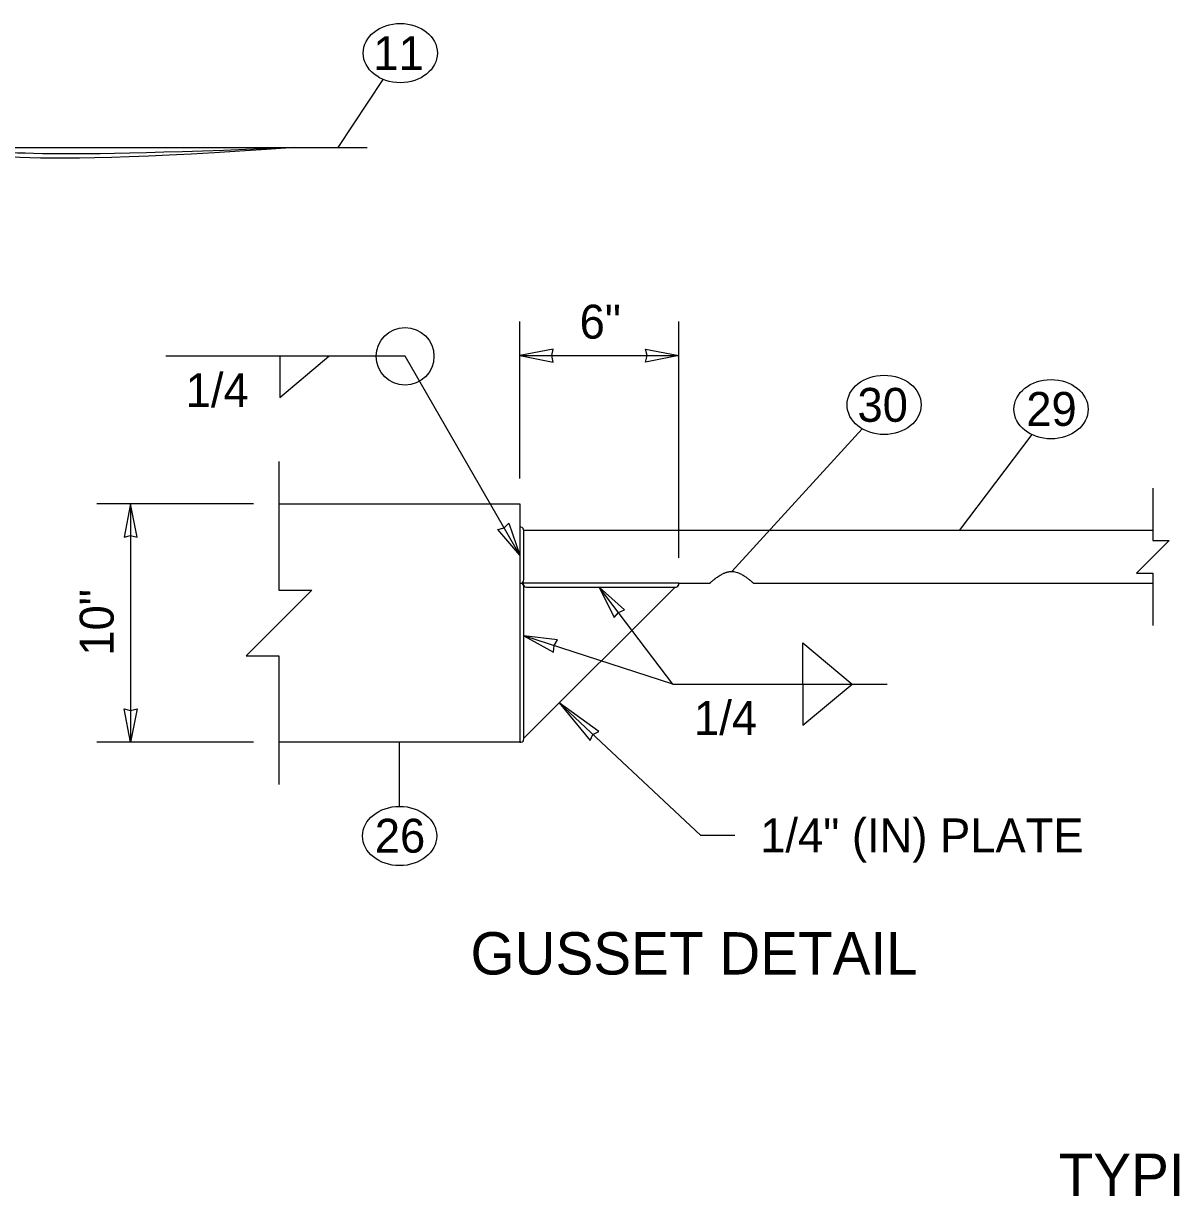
# Model space of a CAD drawing. Extents: x 99862 to 104211, y 98939 to 102076.
# Drawn here: x 102205 to 102749, y 100846 to 101400 of the extents above; entities that cross this region are included whole.
import ezdxf

# ---------------------------------------------------------------- set-up
doc = ezdxf.new("R2010")
doc.units = 0
for name, color, linetype in [('Level 12', 7, 'Continuous'), ('Level 15', 7, 'Continuous'), ('Level 16', 7, 'Continuous'), ('Level 2', 7, 'Continuous'), ('Level 20', 7, 'Continuous'), ('Level 3', 7, 'Continuous'), ('Level 4', 7, 'Continuous'), ('Level 9', 7, 'Continuous')]:
    doc.layers.add(name, color=color, linetype=linetype)

msp = doc.modelspace()

# ---------------------------------------------------------------- linework, layer by layer
at = {"layer": 'Level 12'}
msp.add_line((102123.27, 101341.26), (102367.23, 101341.26), dxfattribs=at)
at = {"layer": 'Level 15'}
for p, q in [((102374.75, 101373.43), (102353.49, 101341.26)), ((102439.43, 101185.03), (102439.43, 101259.03)), ((102514.43, 101147.53), (102514.43, 101259.03)), ((102385.21, 101242.68), (102272.21, 101242.68)), ((102439.43, 101148.76), (102385.21, 101242.68)), ((102439.43, 101243.03), (102514.43, 101243.03)), ((102600.94, 101208.46), (102539.33, 101141.08)), ((102680.98, 101205.72), (102646.64, 101160.43)), ((102313.65, 101173.03), (102239.65, 101173.03)), ((102255.65, 101173.03), (102255.65, 101060.53)), ((102511.56, 101087.97), (102476.83, 101133.7)), ((102511.56, 101087.97), (102441.26, 101110.74)), ((102511.56, 101087.97), (102612.69, 101087.97)), ((102457.93, 101079.03), (102524.79, 101016.5)), ((102313.65, 101060.53), (102239.65, 101060.53)), ((102382.54, 101030.22), (102382.54, 101060.53)), ((102540.79, 101016.5), (102524.79, 101016.5))]:
    msp.add_line(p, q, dxfattribs=at)
for points in [[(102439.43, 101243.03), (102455.15, 101239.95), (102454.43, 101243.03), (102455.15, 101246.11)], [(102514.43, 101243.03), (102498.7, 101239.95), (102499.43, 101243.03), (102498.7, 101246.11)], [(102255.65, 101173.03), (102252.57, 101157.3), (102255.65, 101158.03), (102258.74, 101157.3)], [(102439.43, 101148.76), (102428.9, 101160.84), (102431.93, 101161.75), (102434.24, 101163.92)], [(102476.83, 101133.7), (102483.89, 101119.31), (102485.9, 101121.76), (102488.8, 101123.04)], [(102441.26, 101110.79), (102455.26, 101102.99), (102455.52, 101106.15), (102457.17, 101108.86)], [(102457.93, 101079.03), (102472.56, 101061.25), (102473.83, 101064.16), (102476.64, 101065.61)], [(102255.65, 101060.53), (102252.57, 101076.25), (102255.65, 101075.53), (102258.74, 101076.25)]]:
    msp.add_lwpolyline(points, close=True, dxfattribs=at)
for points in [[(102326.05, 101242.68), (102326.05, 101223.21), (102349.28, 101242.68)], [(102325.65, 101193.03), (102325.65, 101132.27), (102341.14, 101132.27), (102310.17, 101101.29), (102325.65, 101101.29), (102325.65, 101040.53)], [(102738.12, 101180.43), (102738.12, 101155.72), (102745.86, 101155.72), (102730.37, 101140.24), (102738.12, 101140.24), (102738.12, 101115.53)], [(102572.93, 101087.97), (102572.93, 101107.44), (102596.16, 101087.97)], [(102572.93, 101087.97), (102572.93, 101068.5), (102596.16, 101087.97)]]:
    msp.add_lwpolyline(points, dxfattribs=at)
msp.add_circle((102385.21, 101242.68), 13.61, dxfattribs=at)
at = {"layer": 'Level 16'}
for points in [[(102333.14, 101341.26), (102186.03, 101330.44), (102169.52, 101348.95), (102146.65, 101342.91), (102142.45, 101341.28)], [(102333.14, 101341.26), (102203.46, 101335.63), (102169.6, 101342.41), (102160.42, 101347.25), (102150.05, 101341.31)]]:
    msp.add_open_spline(points, degree=3, dxfattribs=at)
at = {"layer": 'Level 2'}
for p, q in [((102325.65, 101173.03), (102439.43, 101173.03)), ((102439.43, 101173.03), (102439.43, 101060.53)), ((102439.43, 101060.53), (102325.65, 101060.53))]:
    msp.add_line(p, q, dxfattribs=at)
at = {"layer": 'Level 20'}
for centre in [(102382.93, 101385.81), (102611.27, 101219.76), (102690.06, 101217.69), (102382.61, 101016.22)]:
    msp.add_ellipse(centre, major_axis=(-17.5, 0), ratio=0.8, dxfattribs=at)
at = {"layer": 'Level 3'}
msp.add_line((102512.6, 101133.7), (102441.26, 101062.36), dxfattribs=at)
at = {"layer": 'Level 4'}
for p, q in [((102738.12, 101160.43), (102441.26, 101160.43)), ((102514.41, 101135.53), (102528.99, 101135.53)), ((102549.67, 101135.53), (102738.12, 101135.53))]:
    msp.add_line(p, q, dxfattribs=at)
msp.add_open_spline([(102528.99, 101135.53), (102528.99, 101135.53), (102528.99, 101135.53), (102528.99, 101135.53), (102529.01, 101135.55), (102529.08, 101135.61), (102529.19, 101135.71), (102529.36, 101135.86), (102529.56, 101136.04), (102529.68, 101136.14), (102530.07, 101136.48), (102530.39, 101136.76), (102530.94, 101137.21), (102531.14, 101137.37), (102531.55, 101137.69), (102532.2, 101138.19), (102532.95, 101138.72), (102534.02, 101139.41), (102534.6, 101139.74), (102535.52, 101140.19), (102535.83, 101140.33), (102536.49, 101140.58), (102536.83, 101140.7), (102537.52, 101140.88), (102537.87, 101140.96), (102538.59, 101141.06), (102538.96, 101141.08), (102540.06, 101141.08), (102540.77, 101140.98), (102542.17, 101140.61), (102542.82, 101140.35), (102544.05, 101139.75), (102544.63, 101139.41), (102545.7, 101138.73), (102546.2, 101138.38), (102546.89, 101137.86), (102547.11, 101137.69), (102547.52, 101137.37), (102547.91, 101137.06), (102548.25, 101136.77), (102548.57, 101136.5), (102548.72, 101136.37), (102548.98, 101136.14), (102549.1, 101136.04), (102549.3, 101135.86), (102549.39, 101135.78), (102549.6, 101135.59), (102549.67, 101135.53), (102549.67, 101135.53)], degree=3, dxfattribs=at)
at = {"layer": 'Level 9'}
for p, q in [((102439.89, 101161.98), (102439.43, 101161.98)), ((102439.43, 101161.98), (102439.43, 101139.52)), ((102439.89, 101161.98), (102439.43, 101161.98)), ((102439.43, 101161.98), (102439.43, 101060.53)), ((102441.26, 101137.09), (102441.26, 101160.43)), ((102441.26, 101137.09), (102441.26, 101160.43)), ((102439.43, 101139.52), (102439.43, 101135.53)), ((102439.43, 101135.53), (102439.7, 101135.53)), ((102439.7, 101135.53), (102439.43, 101135.53)), ((102439.43, 101135.51), (102439.43, 101060.53)), ((102439.7, 101135.51), (102439.44, 101135.51)), ((102439.44, 101135.51), (102439.7, 101135.51)), ((102512.87, 101135.53), (102440.98, 101135.53)), ((102440.98, 101135.53), (102440.98, 101135.26)), ((102512.87, 101135.53), (102440.98, 101135.53)), ((102440.98, 101135.53), (102440.98, 101135.26)), ((102514.41, 101135.53), (102512.87, 101135.53)), ((102514.41, 101135.53), (102512.87, 101135.53)), ((102441.26, 101062.08), (102441.26, 101133.95)), ((102442.55, 101133.7), (102512.87, 101133.7)), ((102439.43, 101060.53), (102439.89, 101060.53)), ((102439.89, 101060.53), (102439.43, 101060.53))]:
    msp.add_line(p, q, dxfattribs=at)
for points in [[(102439.44, 101135.51), (102439.43, 101135.51)], [(102441.26, 101062.08), (102441.26, 101062.36), (102441.26, 101110.74), (102441.26, 101110.79), (102441.26, 101133.95)], [(102442.55, 101133.7), (102476.83, 101133.7), (102512.6, 101133.7), (102512.87, 101133.7)]]:
    msp.add_lwpolyline(points, dxfattribs=at)
for centre, start, end in [((102439.7, 101160.43), 0, 82.6661), ((102439.7, 101160.43), 0, 82.6661), ((102439.7, 101137.09), 270, 0), ((102439.7, 101137.09), 270, 0), ((102439.7, 101133.95), 360, 90), ((102439.7, 101133.95), 0, 90), ((102442.55, 101135.26), 180, 270), ((102442.55, 101135.26), 180, 270), ((102512.87, 101135.26), 270, 9.8961), ((102512.87, 101135.26), 270, 0), ((102512.87, 101135.26), 0, 9.8961), ((102439.7, 101062.08), 277.3339, 0), ((102439.7, 101062.08), 277.3339, 0)]:
    msp.add_arc(centre, 1.56, start, end, dxfattribs=at)

# ---------------------------------------------------------------- texts
at = {"layer": 'Level 20'}
for s, height, p in [('11', 16, (102370.2, 101377.81)), ('6"', 16, (102467.57, 101251.03)), ('1/4', 16, (102281.66, 101218.68)), ('30', 16, (102598.71, 101211.76)), ('29', 16, (102678.36, 101209.83)), ('26', 16, (102370.91, 101008.35)), ('1/4" (IN) PLATE', 16, (102552.79, 101008.5)), ('GUSSET DETAIL', 20, (102416.08, 100950.82)), ('TYPICAL LUMINAIRE MOUNTING', 20, (102693.67, 100846.3))]:
    msp.add_text(s, height=height, dxfattribs=at).set_placement(p)
for s, rotation, p in [('10"', 90, (102247.65, 101101.37)), ('1/4', 360, (102521.57, 101063.97))]:
    msp.add_text(s, height=16, rotation=rotation, dxfattribs=at).set_placement(p)

doc.saveas('drawing.dxf')
